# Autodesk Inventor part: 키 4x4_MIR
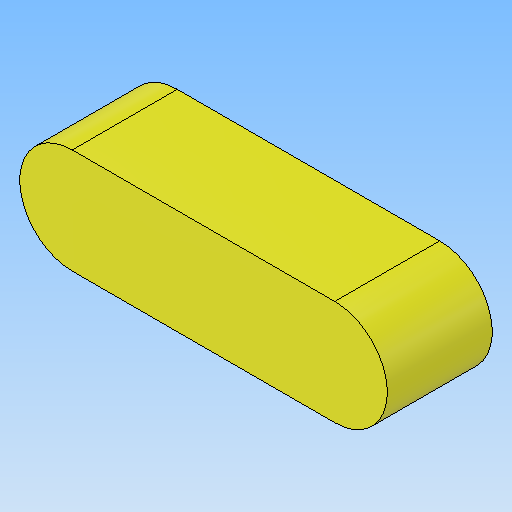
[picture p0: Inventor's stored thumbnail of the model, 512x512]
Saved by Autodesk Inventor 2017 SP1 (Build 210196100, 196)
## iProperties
Created: 2018-09
Part Number: 키 4x4_MIR
Material: 강철, 연강
Document SubType Name: Modeling
Designer: MRC
Density: 7.86 g/cm^3
Appearance: 강철
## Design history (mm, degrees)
derived "키 4x4.ipt"
  sketch "스케치1"
    geometry: L1 (5, -2)-(-5, -2) reference; L2 (-5, 2)-(5, 2) reference; A1 r 2 centre (-5, 0) between (-5, 2) and (-5, -2) reference; A2 r 2 centre (5, 0) between (5, -2) and (5, 2) reference; 2 further points
    dimensions: "d0" = 10 dimension on point (0, 0) L1.start L1.end L1 L2.start A1.centre A1 L2.end L2 A2.centre A2 point (0, -2)
feature "솔리드1::키 4x4.ipt" dims "d0" = 10
tag "피쳐 태그1"
node "솔리드1"
